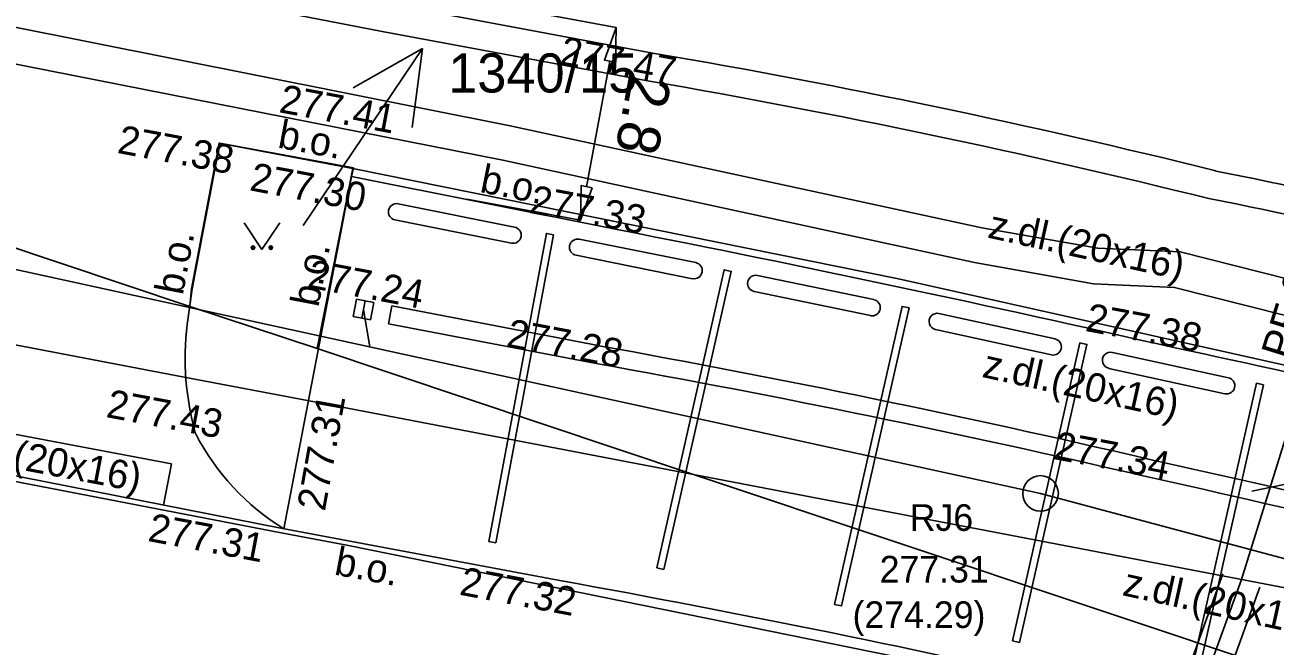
# Model space of a CAD drawing. Extents: x -601602 to -600882, y -1162594 to -1161950.
# Drawn here: x -601194.43 to -601176.86, y -1162089.58 to -1162080.85 of the extents above; entities that cross this region are included whole.
import ezdxf

# ---------------------------------------------------------------- set-up
doc = ezdxf.new("R2010")
doc.units = 0
for name, color, linetype in [('G_ZNACKY', 7, 'Continuous'), ('H_VYSKY_PREVZATE', 7, 'Continuous'), ('IS_KAN_JEDNOTNA', 7, 'Continuous'), ('IS_ODVODNĚNÍ', 7, 'Continuous'), ('IS_VODOVOD_PRIPOJKA', 7, 'Continuous'), ('KN_Hranice parcel', 7, 'Continuous'), ('KN_Parcelní čísla', 7, 'Continuous'), ('KN_Pop  PČ popisy', 7, 'Continuous'), ('KN_Věcná břemena k části', 7, 'Continuous'), ('Vrstva 14', 7, 'Continuous'), ('Vrstva 25', 7, 'Continuous'), ('VRSTVA 40', 7, 'Continuous'), ('Vrstva 7', 7, 'Continuous')]:
    doc.layers.add(name, color=color, linetype=linetype)

# ---------------------------------------------------------------- blocks, each defined once
blk = doc.blocks.new('1029_33')
at = {"layer": 'KN_Pop  PČ popisy'}
for p, q in [((0, 0), (1.678, 2.488)), ((1.678, 2.488), (0.703, 1.938)), ((1.678, 2.488), (1.533, 1.378))]:
    blk.add_line(p, q, dxfattribs=at)

msp = doc.modelspace()

# ---------------------------------------------------------------- linework, layer by layer
at = {"layer": 'G_ZNACKY'}
msp.add_circle((-601180.153, -1162087.436), 0.25, dxfattribs=at)
at = {"layer": 'IS_KAN_JEDNOTNA'}
msp.add_lwpolyline([(-601284.233, -1162104.983), (-601281.181, -1162099.025), (-601277.302, -1162081.896), (-601264.676, -1162070.309), (-601240.903, -1162074.739), (-601224.554, -1162077.728), (-601180.153, -1162087.436), (-601164.522, -1162091.613), (-601134.295, -1162101.261)], dxfattribs=at)
at = {"layer": 'IS_ODVODNĚNÍ'}
msp.add_line((-601189.67, -1162084.85), (-601189.58, -1162085.375), dxfattribs=at)
at = {"layer": 'IS_VODOVOD_PRIPOJKA'}
for p, q in [((-601180.397, -1162096.305), (-601177.591, -1162088.567)), ((-601179.879, -1162096.493), (-601177.073, -1162088.755))]:
    msp.add_line(p, q, dxfattribs=at)
msp.add_lwpolyline([(-601180.206, -1162096.609), (-601180.138, -1162096.399), (-601180.083, -1162096.238), (-601177.332, -1162088.661), (-601174.614, -1162079.923)], dxfattribs=at)
at = {"layer": 'KN_Hranice parcel'}
for p, q in [((-601190.32, -1162085.4), (-601189.82, -1162082.87)), ((-601192.11, -1162084.81), (-601195.48, -1162083.68)), ((-601190.32, -1162085.4), (-601192.11, -1162084.81)), ((-601185.03, -1162087.17), (-601190.32, -1162085.4)), ((-601162.97, -1162094.53), (-601185.03, -1162087.17))]:
    msp.add_line(p, q, dxfattribs=at)
for points in [[(-601185.03, -1162087.17), (-601190.46, -1162086.13), (-601192.19, -1162085.8), (-601195.87, -1162085.1), (-601197.57, -1162084.78), (-601219.47, -1162080.6), (-601220.77, -1162080.2)], [(-601192.11, -1162084.81), (-601192.09, -1162084.56), (-601191.7, -1162082.51), (-601189.82, -1162082.87)], [(-601216.97, -1162082.96), (-601197.87, -1162086.63), (-601190.83, -1162087.99), (-601189.88, -1162088.17), (-601179.25, -1162090.33), (-601172.41, -1162091.94), (-601162.97, -1162094.53)], [(-601189.82, -1162082.87), (-601182.15, -1162084.42), (-601174.31, -1162086.17), (-601166.57, -1162088.14), (-601162.76, -1162089.28), (-601132.72, -1162099.21)], [(-601155.45, -1162095.09), (-601166.29, -1162091.48), (-601172.28, -1162089.73), (-601176.47, -1162088.81), (-601185.03, -1162087.17)]]:
    msp.add_lwpolyline(points, dxfattribs=at)
at = {"layer": 'KN_Věcná břemena k části'}
for points in [[(-601153.16, -1162090.88), (-601155.94, -1162088.96), (-601156.93, -1162088.27), (-601164.39, -1162086.81), (-601166.38, -1162087.03), (-601178.19, -1162084.04), (-601179.35, -1162083.99), (-601180.98, -1162083.7), (-601187.61, -1162082.27), (-601194.69, -1162080.86)], [(-601194.77, -1162081.36), (-601187.71, -1162082.75), (-601181.08, -1162084.19), (-601179.41, -1162084.49), (-601178.27, -1162084.54), (-601166.42, -1162087.53), (-601164.71, -1162087.35), (-601165.04, -1162088.85), (-601165.84, -1162091.63)]]:
    msp.add_lwpolyline(points, dxfattribs=at)
at = {"layer": 'Vrstva 14'}
for p, q in [((-601191.348, -1162083.63), (-601191.098, -1162084.005)), ((-601191.098, -1162084.005), (-601190.848, -1162083.63))]:
    msp.add_line(p, q, dxfattribs=at)
for points in [[(-601191.223, -1162084.005), (-601191.248, -1162083.98), (-601191.223, -1162083.955)], [(-601191.223, -1162084.005), (-601191.223, -1162083.955), (-601191.198, -1162083.98)], [(-601190.973, -1162084.005), (-601190.998, -1162083.98), (-601190.973, -1162083.955)], [(-601190.973, -1162084.005), (-601190.973, -1162083.955), (-601190.948, -1162083.98)]]:
    msp.add_lwpolyline(points, close=True, dxfattribs=at)
for centre in [(-601191.223, -1162083.98), (-601190.973, -1162083.98)]:
    msp.add_circle(centre, 0.025, dxfattribs=at)
at = {"layer": 'Vrstva 25'}
for p, q in [((-601189.769, -1162084.703), (-601189.818, -1162084.948)), ((-601189.523, -1162084.752), (-601189.769, -1162084.703)), ((-601189.769, -1162084.703), (-601189.769, -1162084.703)), ((-601189.645, -1162084.727), (-601189.695, -1162084.973)), ((-601189.572, -1162084.997), (-601189.523, -1162084.752)), ((-601189.818, -1162084.948), (-601189.572, -1162084.997))]:
    msp.add_line(p, q, dxfattribs=at)
at = {"layer": 'VRSTVA 40'}
for p, q in [((-601187.716, -1162080.589), (-601186.119, -1162080.885)), ((-601186.206, -1162081.357), (-601186.534, -1162083.124)), ((-601188.218, -1162083.299), (-601186.622, -1162083.596))]:
    msp.add_line(p, q, dxfattribs=at)
for points in [[(-601186.128, -1162081.372), (-601186.285, -1162081.343), (-601186.119, -1162080.885)], [(-601186.455, -1162083.138), (-601186.613, -1162083.109), (-601186.622, -1162083.596)]]:
    msp.add_lwpolyline(points, close=True, dxfattribs=at)
at = {"layer": 'Vrstva 7'}
for p, q in [((-601196.47, -1162079.57), (-601189.41, -1162080.94)), ((-601189.34, -1162080.55), (-601185.58, -1162081.25)), ((-601189.41, -1162080.94), (-601185.65, -1162081.64)), ((-601192.08, -1162084.56), (-601191.69, -1162082.51)), ((-601191.69, -1162082.51), (-601189.81, -1162082.86)), ((-601189.81, -1162082.86), (-601189.84, -1162082.98)), ((-601190.792, -1162087.933), (-601189.84, -1162082.98)), ((-601189.84, -1162082.98), (-601186.08, -1162083.73)), ((-601189.183, -1162083.364), (-601187.546, -1162083.692)), ((-601187.591, -1162083.918), (-601189.229, -1162083.589)), ((-601186.637, -1162083.863), (-601185, -1162084.191)), ((-601185.045, -1162084.417), (-601186.683, -1162084.088)), ((-601184.133, -1162084.372), (-601182.498, -1162084.712)), ((-601192.15, -1162085.06), (-601192.08, -1162084.56)), ((-601182.544, -1162084.937), (-601184.179, -1162084.597)), ((-601189.32, -1162085.05), (-601189.27, -1162084.8)), ((-601189.27, -1162084.8), (-601186.35, -1162085.36)), ((-601181.582, -1162084.907), (-601179.95, -1162085.264)), ((-601189.32, -1162085.05), (-601186.4, -1162085.61)), ((-601179.999, -1162085.489), (-601181.631, -1162085.132)), ((-601179.144, -1162085.453), (-601177.513, -1162085.81)), ((-601177.562, -1162086.035), (-601179.193, -1162085.678)), ((-601196.06, -1162086.32), (-601192.37, -1162087.02)), ((-601197.84, -1162086.54), (-601190.81, -1162087.93)), ((-601192.37, -1162087.02), (-601192.48, -1162087.6)), ((-601176.127, -1162087.183), (-601177.185, -1162087.405)), ((-601190.81, -1162087.93), (-601186.91, -1162088.66))]:
    msp.add_line(p, q, dxfattribs=at)
for points in [[(-601187.001, -1162083.799), (-601187.811, -1162088.129), (-601187.909, -1162088.111), (-601187.099, -1162083.781)], [(-601185.549, -1162088.482), (-601184.599, -1162084.292), (-601184.501, -1162084.314), (-601185.451, -1162088.504)], [(-601183.049, -1162088.996), (-601182.099, -1162084.806), (-601182.001, -1162084.828), (-601182.951, -1162089.018)], [(-601180.549, -1162089.509), (-601179.599, -1162085.319), (-601179.501, -1162085.341), (-601180.451, -1162089.531)], [(-601177.019, -1162085.909), (-601177.976, -1162090.145), (-601178.073, -1162090.123), (-601177.116, -1162085.886)]]:
    msp.add_lwpolyline(points, close=True, dxfattribs=at)
for centre, radius, start, end in [((-601316.234, -1162688.106), 623.453, 76.572769, 77.107686), ((-601204.175, -1162189.855), 110.186, 76.092, 80.28444), ((-601204.442, -1162190.706), 110.673, 76.06503, 80.22379), ((-601196.382, -1162177.217), 96.147, 75.09662, 78.80192), ((-601189.206, -1162083.477), 0.115, 78.6491, 258.6491), ((-601197.207, -1162180.752), 99.378, 75.11758, 78.73253), ((-601187.569, -1162083.805), 0.115, 258.6491, 78.6491), ((-601234.957, -1162333.231), 254.243, 77.11455, 78.91619), ((-601186.66, -1162083.975), 0.115, 78.6491, 258.6491), ((-601185.023, -1162084.304), 0.115, 258.6491, 78.6491), ((-601184.156, -1162084.484), 0.115, 78.2379, 258.2379), ((-601182.521, -1162084.825), 0.115, 258.2379, 78.2379), ((-601181.606, -1162085.019), 0.115, 77.6641, 257.6641), ((-601188.197, -1162085.527), 3.981, 173.2678, 195.6434), ((-601179.975, -1162085.376), 0.115, 257.6641, 77.6641), ((-601213.834, -1162238.069), 155.161, 76.89386, 79.80113), ((-601179.169, -1162085.565), 0.115, 77.6641, 257.6641), ((-601207.358, -1162223.372), 141.017, 75.41366, 78.09179), ((-601213.57, -1162237.354), 154.158, 76.93041, 79.84857), ((-601177.537, -1162085.922), 0.115, 257.6641, 77.6641), ((-601189.001, -1162085.03), 3.411, 207.3988, 238.3268), ((-601214.246, -1162249.707), 166.602, 75.29881, 77.66657), ((-601217.664, -1162263.51), 180.572, 75.34666, 77.54185), ((-601218.466, -1162262.792), 176.968, 77.21704, 79.72849)]:
    msp.add_arc(centre, radius, start, end, dxfattribs=at)

# ---------------------------------------------------------------- block references
at = {"layer": 'KN_Pop  PČ popisy'}
msp.add_blockref('1029_33', (-601190.52, -1162083.67), dxfattribs=at)

# ---------------------------------------------------------------- texts
at = {"layer": 'H_VYSKY_PREVZATE'}
for s, rotation, p in [('277.47 ', 349.3397, (-601186.927, -1162081.4)), ('277.41 ', 349.3397, (-601190.871, -1162082.075)), ('277.38 ', 349.3397, (-601193.145, -1162082.647)), ('277.30 ', 349.3397, (-601191.285, -1162083.173)), ('277.33 ', 349.3397, (-601187.352, -1162083.491)), ('277.24 ', 349.3397, (-601190.474, -1162084.538)), ('277.38 ', 349.3397, (-601179.537, -1162085.15)), ('277.28 ', 349.3397, (-601187.677, -1162085.37)), ('277.43 ', 349.3397, (-601193.302, -1162086.361)), ('277.31 ', 79.7767, (-601190.214, -1162087.697)), ('277.34 ', 349.3397, (-601179.987, -1162086.95)), ('277.31 ', 349.3397, (-601192.715, -1162088.103)), ('277.32 ', 349.3397, (-601188.335, -1162088.858))]:
    msp.add_text(s, height=0.4, rotation=rotation, dxfattribs=at).set_placement(p)
at = {"layer": 'IS_KAN_JEDNOTNA'}
for s, p in [('RJ6', (-601181.992, -1162087.963)), ('277.31', (-601182.415, -1162088.689)), ('(274.29)', (-601182.796, -1162089.328))]:
    msp.add_text(s, height=0.375, dxfattribs=at).set_placement(p)
at = {"layer": 'IS_VODOVOD_PRIPOJKA'}
msp.add_text('PE 90', height=0.425, rotation=72.7214, dxfattribs=at).set_placement((-601176.653, -1162085.574))
at = {"layer": 'KN_Parcelní čísla'}
msp.add_text('1340/15', height=0.55, dxfattribs=at).set_placement((-601188.48, -1162081.8))
at = {"layer": 'VRSTVA 40'}
msp.add_text('2.8', height=0.6, rotation=259.4909, dxfattribs=at).set_placement((-601185.929, -1162081.509))
at = {"layer": 'Vrstva 7'}
for s, rotation, p in [('b.o.', 349.454, (-601190.89, -1162082.572)), ('b.o.', 348.7194, (-601188.049, -1162083.197)), ('z.dl.(20x16)', 347.5903, (-601180.91, -1162083.837)), ('b.o.', 79.2285, (-601192.212, -1162084.66)), ('b.o.', 79.1157, (-601190.305, -1162084.829)), ('z.dl.(20x16)', 347.5903, (-601180.988, -1162085.797)), ('r.z.dl.(20x16)', 349.2585, (-601195.902, -1162086.836)), ('b.o.', 349.3981, (-601190.095, -1162088.575)), ('z.dl.(20x16)', 347.5903, (-601179.016, -1162088.865))]:
    msp.add_text(s, height=0.4, rotation=rotation, dxfattribs=at).set_placement(p)

doc.saveas('drawing.dxf')
